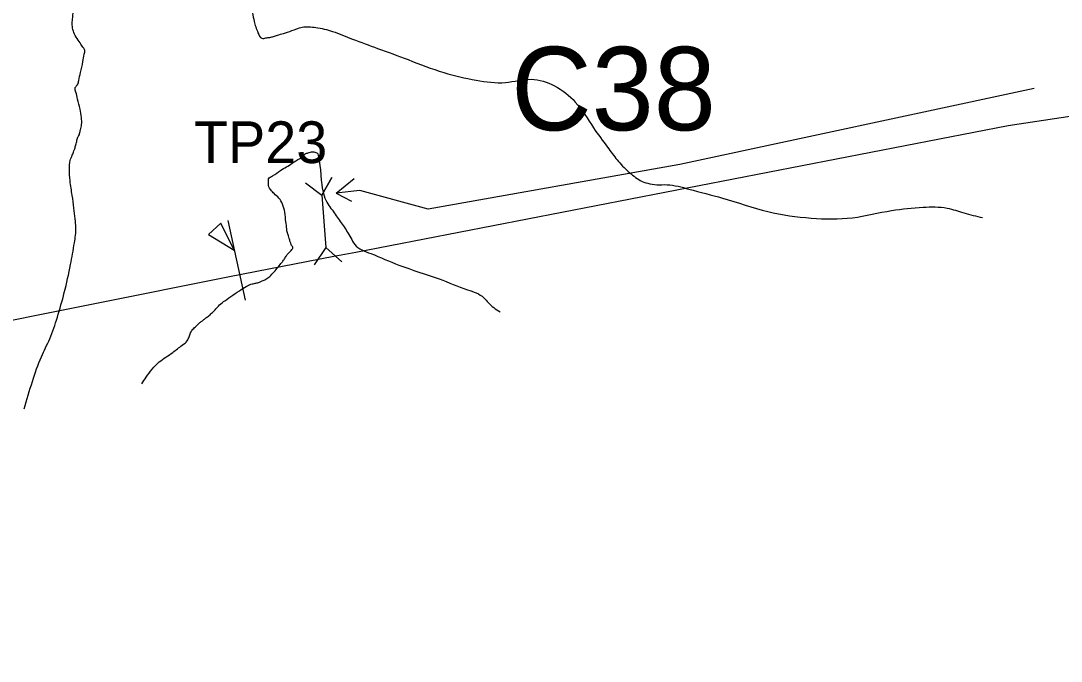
# Model space of a CAD drawing. Extents: x -478645 to -472650, y -1118147 to -1113892.
# Drawn here: x -474629.9 to -474380.6, y -1116081.6 to -1115928.1 of the extents above; entities that cross this region are included whole.
import ezdxf

# ---------------------------------------------------------------- set-up
doc = ezdxf.new("R2010")
doc.units = 0
for name, color, linetype in [('cestní_příkop_návrh', 7, 'Continuous'), ('cesty', 7, 'Continuous'), ('ObPÚ', 7, 'Continuous'), ('TP _navrh', 7, 'Continuous'), ('Vrstevnice_hlavni', 7, 'Continuous'), ('Vrstevnice_vedlejsi', 7, 'Continuous')]:
    doc.layers.add(name, color=color, linetype=linetype)

msp = doc.modelspace()

# ---------------------------------------------------------------- linework, layer by layer
at = {"layer": 'cestní_příkop_návrh'}
msp.add_line((-474554.364, -1115969.411), (-474550.7, -1115971.352), dxfattribs=at)
msp.add_lwpolyline([(-474387.095, -1115944.37), (-474471.978, -1115962.602), (-474532.276, -1115973.242), (-474548.717, -1115968.785), (-474554.364, -1115969.411), (-474550.075, -1115965.942)], dxfattribs=at)
at = {"layer": 'cesty'}
for p, q in [((-474581.987, -1115976.639), (-474584.96, -1115979.315)), ((-474576.091, -1115995.114), (-474580.27, -1115975.978))]:
    msp.add_line(p, q, dxfattribs=at)
msp.add_lwpolyline([(-474584.96, -1115979.315), (-474578.826, -1115983.14), (-474581.987, -1115976.639)], dxfattribs=at)
at = {"layer": 'ObPÚ'}
msp.add_lwpolyline([(-474167.52, -1115928.81), (-474235.6, -1115931.63), (-474334.6, -1115944.44), (-474393.33, -1115953.28), (-474549.61, -1115983.63), (-474554.95, -1115984.66), (-474579.89, -1115989.47), (-474710.27, -1116015.62), (-474751.15, -1116030.18), (-474843.39, -1116079.89), (-474965.66, -1116145.86), (-474947.38, -1116225.55), (-474940.31, -1116265.1), (-474933.9, -1116305.08)], dxfattribs=at)
at = {"layer": 'TP _navrh'}
msp.add_lwpolyline([(-474561.742, -1115966.931), (-474557.815, -1115969.935), (-474555.427, -1115965.721), (-474557.815, -1115969.935), (-474556.8, -1115982.484), (-474552.987, -1115985.926), (-474556.8, -1115982.484), (-474559.591, -1115986.607)], dxfattribs=at)
at = {"layer": 'Vrstevnice_hlavni'}
msp.add_spline([(-474568.708, -1115897.409), (-474572.641, -1115895.541), (-474576.773, -1115894.198), (-474583.071, -1115892.446), (-474591.536, -1115890.285), (-474598.745, -1115889.798), (-474604.699, -1115890.985), (-474609.398, -1115893.846), (-474612.893, -1115895.737), (-474615.185, -1115896.658), (-474616.274, -1115896.608), (-474619.509, -1115894.917), (-474624.892, -1115891.583), (-474632.423, -1115886.608), (-474637.481, -1115883.329), (-474640.068, -1115881.745), (-474640.182, -1115881.857), (-474640.331, -1115882.047), (-474640.513, -1115882.313), (-474640.73, -1115882.656), (-474640.989, -1115882.897), (-474641.292, -1115883.036), (-474641.637, -1115883.072), (-474642.202, -1115883.183), (-474642.986, -1115883.368), (-474643.99, -1115883.627), (-474646.844, -1115884.633), (-474651.549, -1115886.388), (-474658.104, -1115888.89), (-474662.585, -1115890.48), (-474664.99, -1115891.157), (-474665.321, -1115890.923), (-474665.809, -1115890.727), (-474666.454, -1115890.571), (-474667.256, -1115890.453), (-474668.244, -1115890.247), (-474669.42, -1115889.951), (-474670.782, -1115889.566), (-474671.915, -1115889.244), (-474672.82, -1115888.985), (-474673.497, -1115888.789), (-474673.835, -1115888.942), (-474673.833, -1115889.444), (-474673.493, -1115890.295), (-474673.215, -1115890.936), (-474673.001, -1115891.367), (-474672.849, -1115891.589), (-474672.512, -1115892.546), (-474671.987, -1115894.239), (-474671.277, -1115896.668), (-474670.558, -1115898.65), (-474669.829, -1115900.184), (-474669.092, -1115901.271), (-474668.395, -1115902.471), (-474667.739, -1115903.785), (-474667.123, -1115905.213), (-474666.45, -1115906.489), (-474665.719, -1115907.612), (-474664.931, -1115908.583), (-474664.177, -1115909.82), (-474663.458, -1115911.322), (-474662.774, -1115913.09), (-474662.292, -1115914.312), (-474662.011, -1115914.988), (-474661.933, -1115915.117), (-474661.853, -1115915.243), (-474661.769, -1115915.365), (-474661.683, -1115915.483), (-474661.286, -1115916.041), (-474660.577, -1115917.037), (-474659.557, -1115918.473), (-474658.608, -1115919.845), (-474657.73, -1115921.152), (-474656.924, -1115922.395), (-474656.312, -1115923.337), (-474655.894, -1115923.977), (-474655.671, -1115924.316), (-474655.481, -1115924.615), (-474655.324, -1115924.875), (-474655.2, -1115925.095), (-474654.821, -1115926.041), (-474654.189, -1115927.714), (-474653.303, -1115930.113), (-474652.485, -1115932.428), (-474651.736, -1115934.66), (-474651.055, -1115936.809), (-474650.467, -1115940.58), (-474649.971, -1115945.972), (-474649.567, -1115952.986), (-474649.101, -1115958.483), (-474648.572, -1115962.463), (-474647.981, -1115964.927), (-474647.337, -1115970.192), (-474646.64, -1115978.26), (-474645.891, -1115989.13), (-474645.422, -1115996.979), (-474645.235, -1116001.807)], degree=3, dxfattribs=at)
at = {"layer": 'Vrstevnice_vedlejsi'}
for points in [[(-474209.034, -1115951.03), (-474211.313, -1115950.168), (-474219.221, -1115947.128), (-474229.61, -1115943.088), (-474237.423, -1115939.164), (-474242.658, -1115935.356), (-474245.316, -1115931.665), (-474248.923, -1115928.318), (-474253.479, -1115925.316), (-474258.984, -1115922.658), (-474263.708, -1115920.216), (-474267.649, -1115917.989), (-474270.809, -1115915.979), (-474273.585, -1115914.504), (-474275.979, -1115913.566), (-474277.989, -1115913.164), (-474281.053, -1115911.977), (-474285.17, -1115910.005), (-474290.34, -1115907.247), (-474296.508, -1115904.048), (-474303.673, -1115900.408), (-474311.837, -1115896.327), (-474318.145, -1115893.111), (-474322.597, -1115890.761), (-474325.195, -1115889.276), (-474328.177, -1115887.421), (-474331.544, -1115885.195), (-474335.296, -1115882.597), (-474339.214, -1115879.955), (-474343.299, -1115877.267), (-474347.55, -1115874.534), (-474351.295, -1115870.131), (-474354.534, -1115864.058), (-474357.267, -1115856.315), (-474360.518, -1115850.2), (-474364.286, -1115845.714), (-474368.571, -1115842.857), (-474374.444, -1115840.317), (-474381.905, -1115838.095), (-474390.952, -1115836.19), (-474398.081, -1115835.556), (-474403.29, -1115836.19), (-474406.58, -1115838.095), (-474412.121, -1115842.872), (-474419.913, -1115850.522), (-474429.957, -1115861.043), (-474437.287, -1115868.36), (-474441.905, -1115872.472), (-474443.81, -1115873.379), (-474448.889, -1115873.864), (-474457.143, -1115873.929), (-474468.571, -1115873.571), (-474479.637, -1115874.087), (-474490.34, -1115875.476), (-474500.68, -1115877.738), (-474508.571, -1115879.451), (-474514.014, -1115880.616), (-474517.007, -1115881.232), (-474520.166, -1115881.438), (-474523.492, -1115881.232), (-474526.984, -1115880.616), (-474532.593, -1115879.713), (-474540.317, -1115878.524), (-474550.159, -1115877.048), (-474559.76, -1115875.151), (-474569.121, -1115872.835), (-474578.242, -1115870.099), (-474585.726, -1115867.981), (-474591.575, -1115866.481)], [(-474591.575, -1115866.481), (-474595.788, -1115865.599), (-474601.77, -1115863.535), (-474609.524, -1115860.288), (-474619.048, -1115855.858), (-474626.667, -1115852.548), (-474632.381, -1115850.357), (-474636.19, -1115849.286), (-474640.078, -1115848.711), (-474644.043, -1115848.633), (-474648.086, -1115849.051), (-474651.146, -1115849.274), (-474653.223, -1115849.3), (-474654.317, -1115849.13), (-474657.926, -1115849.192), (-474664.05, -1115849.487), (-474672.688, -1115850.014), (-474678.68, -1115850.128), (-474682.025, -1115849.829), (-474682.724, -1115849.116), (-474683.592, -1115848.647), (-474684.628, -1115848.421), (-474685.832, -1115848.438), (-474687.093, -1115848.462), (-474688.409, -1115848.493), (-474689.782, -1115848.531), (-474691.078, -1115848.571), (-474692.299, -1115848.613), (-474693.444, -1115848.657), (-474694.215, -1115848.685), (-474694.61, -1115848.699), (-474694.63, -1115848.696), (-474694.647, -1115848.692), (-474694.661, -1115848.686), (-474694.671, -1115848.678), (-474694.808, -1115848.542), (-474695.072, -1115848.278), (-474695.462, -1115847.886), (-474696.141, -1115847.639), (-474697.107, -1115847.538), (-474698.362, -1115847.582), (-474699.498, -1115847.597), (-474700.518, -1115847.583), (-474701.419, -1115847.538), (-474702.233, -1115847.469), (-474702.96, -1115847.376), (-474703.598, -1115847.257), (-474704.705, -1115847.616), (-474706.279, -1115848.453), (-474708.321, -1115849.767), (-474709.743, -1115850.694), (-474710.545, -1115851.234), (-474710.727, -1115851.387), (-474710.858, -1115851.503), (-474710.938, -1115851.581), (-474710.968, -1115851.623), (-474711.204, -1115851.74), (-474711.646, -1115851.932), (-474712.295, -1115852.199), (-474712.883, -1115854.065), (-474713.412, -1115857.529), (-474713.88, -1115862.59), (-474714.273, -1115866.826), (-474714.591, -1115870.235), (-474714.833, -1115872.818), (-474714.931, -1115874.799), (-474714.887, -1115876.179), (-474714.698, -1115876.958), (-474714.494, -1115877.673), (-474714.274, -1115878.323), (-474714.038, -1115878.91), (-474713.675, -1115879.511), (-474713.183, -1115880.126), (-474712.564, -1115880.755), (-474710.648, -1115882.692), (-474707.436, -1115885.938), (-474702.927, -1115890.492), (-474699.422, -1115893.985), (-474696.92, -1115896.419), (-474695.421, -1115897.793), (-474693.034, -1115901.023), (-474689.758, -1115906.111), (-474685.593, -1115913.055), (-474682.658, -1115918.139), (-474680.952, -1115921.361), (-474680.476, -1115922.721), (-474679.276, -1115926.308), (-474677.35, -1115932.121), (-474674.701, -1115940.161), (-474672.818, -1115945.835), (-474671.702, -1115949.145), (-474671.353, -1115950.09), (-474671.046, -1115950.953), (-474670.782, -1115951.736), (-474670.56, -1115952.436), (-474670.368, -1115953.666), (-474670.206, -1115955.425)], [(-474629.163, -1116021.122), (-474627.138, -1116014.553), (-474625.004, -1116008.664), (-474623.005, -1116004.332), (-474621.174, -1115999.201), (-474619.512, -1115993.271), (-474618.018, -1115986.542), (-474617.087, -1115981.356), (-474616.718, -1115977.714), (-474616.912, -1115975.614), (-474617.211, -1115973.036), (-474617.616, -1115969.978), (-474618.126, -1115966.442), (-474618.292, -1115963.658), (-474618.114, -1115961.626), (-474617.591, -1115960.345), (-474617.2, -1115959.334), (-474616.941, -1115958.594), (-474616.813, -1115958.125), (-474616.681, -1115957.613), (-474616.546, -1115957.06), (-474616.407, -1115956.465), (-474616.271, -1115956.027), (-474616.137, -1115955.746), (-474616.007, -1115955.622), (-474615.835, -1115955.118), (-474615.622, -1115954.234), (-474615.368, -1115952.971), (-474615.405, -1115951.324), (-474615.732, -1115949.293), (-474616.351, -1115946.88), (-474616.748, -1115945.218), (-474616.923, -1115944.306), (-474616.877, -1115944.145), (-474616.768, -1115943.95), (-474616.598, -1115943.72), (-474616.365, -1115943.456), (-474616.032, -1115942.4), (-474615.599, -1115940.552), (-474615.066, -1115937.913), (-474614.734, -1115936.109), (-474614.601, -1115935.141), (-474614.668, -1115935.007), (-474615.04, -1115934.443), (-474615.716, -1115933.448), (-474616.696, -1115932.022), (-474617.324, -1115930.586), (-474617.601, -1115929.14), (-474617.525, -1115927.684), (-474617.418, -1115926.35), (-474617.28, -1115925.139), (-474617.111, -1115924.051), (-474616.992, -1115923.053), (-474616.924, -1115922.146), (-474616.906, -1115921.33), (-474615.018, -1115919.643), (-474611.259, -1115917.085), (-474605.63, -1115913.657), (-474601.012, -1115911.593), (-474597.406, -1115910.892), (-474594.811, -1115911.554), (-474591.261, -1115912.861), (-474586.755, -1115914.811), (-474581.293, -1115917.406), (-474577.348, -1115920.514), (-474574.921, -1115924.137), (-474574.012, -1115928.275), (-474573.09, -1115931.005), (-474572.156, -1115932.327), (-474571.209, -1115932.241), (-474570.271, -1115932.091), (-474569.342, -1115931.876)], [(-474569.342, -1115931.876), (-474568.423, -1115931.595), (-474566.976, -1115931.134), (-474565.002, -1115930.492), (-474562.501, -1115929.669), (-474559.242, -1115929.729), (-474555.226, -1115930.672), (-474550.451, -1115932.497), (-474544.416, -1115934.752), (-474537.118, -1115937.435), (-474528.559, -1115940.548), (-474520.787, -1115942.372), (-474513.802, -1115942.909), (-474507.604, -1115942.157), (-474502.014, -1115943.723), (-474497.031, -1115947.604), (-474492.656, -1115953.802), (-474489.308, -1115958.423), (-474486.987, -1115961.466), (-474485.693, -1115962.933), (-474484.342, -1115964.245), (-474482.933, -1115965.403), (-474481.466, -1115966.406), (-474479.666, -1115967.075), (-474477.53, -1115967.409), (-474475.06, -1115967.409), (-474469.793, -1115968.482), (-474461.727, -1115970.628), (-474450.864, -1115973.847), (-474440.494, -1115975.414), (-474430.618, -1115975.328), (-474421.236, -1115973.591), (-474413.664, -1115972.82), (-474407.902, -1115973.016), (-474403.951, -1115974.178), (-474399.418, -1115975.28)], [(-474570.595, -1115966.382), (-474570.552, -1115966.045), (-474569.586, -1115965.25), (-474567.696, -1115963.997), (-474564.883, -1115962.286), (-474563.001, -1115961.1), (-474562.049, -1115960.438), (-474562.027, -1115960.3), (-474561.966, -1115960.182), (-474561.863, -1115960.083), (-474561.721, -1115960.003), (-474561.45, -1115959.892), (-474561.052, -1115959.75), (-474560.526, -1115959.577), (-474560.002, -1115959.528), (-474559.481, -1115959.603), (-474558.961, -1115959.801), (-474558.523, -1115961.066), (-474558.168, -1115963.395), (-474557.894, -1115966.79), (-474557.375, -1115969.537), (-474556.611, -1115971.636), (-474555.601, -1115973.086), (-474554.612, -1115974.495), (-474553.643, -1115975.863), (-474552.696, -1115977.189), (-474551.758, -1115978.61), (-474550.83, -1115980.126), (-474549.912, -1115981.737), (-474546.078, -1115983.919), (-474539.329, -1115986.671), (-474529.664, -1115989.994), (-474522.873, -1115992.603), (-474518.956, -1115994.5), (-474517.911, -1115995.683), (-474515.084, -1115997.907)], [(-474600.956, -1116015.137), (-474599.892, -1116013.554), (-474596.752, -1116009.907), (-474593.504, -1116007.607), (-474591.262, -1116005.909), (-474590.027, -1116004.814), (-474589.798, -1116004.321), (-474589.589, -1116003.838), (-474589.398, -1116003.363), (-474589.227, -1116002.898), (-474588.988, -1116002.461), (-474588.681, -1116002.052), (-474588.307, -1116001.671), (-474587.901, -1116001.28), (-474587.463, -1116000.88), (-474586.993, -1116000.47), (-474586.422, -1116000.005), (-474585.752, -1115999.483), (-474584.981, -1115998.905), (-474584.194, -1115998.217), (-474583.392, -1115997.42), (-474582.575, -1115996.513), (-474581.322, -1115995.444), (-474579.634, -1115994.211), (-474577.51, -1115992.815), (-474575.901, -1115991.838), (-474574.806, -1115991.279), (-474574.226, -1115991.139), (-474573.757, -1115991.032), (-474573.4, -1115990.957), (-474573.154, -1115990.915), (-474572.707, -1115990.755), (-474572.06, -1115990.477), (-474571.212, -1115990.079), (-474570.285, -1115989.381), (-474569.278, -1115988.38), (-474568.191, -1115987.078), (-474567.383, -1115986.069), (-474566.854, -1115985.354), (-474566.604, -1115984.933), (-474566.374, -1115984.578), (-474566.166, -1115984.287), (-474565.979, -1115984.061), (-474565.715, -1115983.767), (-474565.375, -1115983.406), (-474564.959, -1115982.976), (-474564.747, -1115982.624), (-474564.737, -1115982.35), (-474564.93, -1115982.154), (-474565.136, -1115981.742), (-474565.355, -1115981.116), (-474565.587, -1115980.274), (-474565.778, -1115979.629), (-474565.929, -1115979.18), (-474566.04, -1115978.928), (-474566.198, -1115977.981), (-474566.405, -1115976.34), (-474566.66, -1115974.005), (-474567.217, -1115972.093), (-474568.075, -1115970.604), (-474569.236, -1115969.539), (-474570.036, -1115968.634), (-474570.477, -1115967.889), (-474570.557, -1115967.303), (-474570.596, -1115966.801), (-474570.595, -1115966.382)]]:
    msp.add_spline(points, degree=3, dxfattribs=at)

# ---------------------------------------------------------------- texts
at = {"layer": 'cesty'}
msp.add_text('C38', height=20, rotation=359.99999, dxfattribs=at).set_placement((-474512.42, -1115954.37))
at = {"layer": 'TP _navrh'}
msp.add_text('TP23', height=10, rotation=359.99999, dxfattribs=at).set_placement((-474588.439, -1115962.227))

doc.saveas('drawing.dxf')
